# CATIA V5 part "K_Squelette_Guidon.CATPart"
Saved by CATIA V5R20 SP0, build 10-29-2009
Part number: Squelette_Guidon
Bounding box of the stored display mesh (mm): x -220 to 220, y 0 to 0, z 0 to 150
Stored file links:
  G:\Khaled_CFAO_2011\ST2M\ST2M_GR1\bmartinez\Khaled\CAD_ThinkMOTION\K_Squelette_Guidon.CATPart
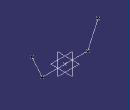
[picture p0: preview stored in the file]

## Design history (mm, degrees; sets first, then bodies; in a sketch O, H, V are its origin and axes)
Set1
  Point1: type OnPlane, Support xy-plane, H 150, V 0, Direction (1, 0, 0)
  Point2: type OnPlane, Support xy-plane, H -150, V 0, Direction (1, 0, 0)
  Line1: type PtPt, FirstPoint Point2, SecondPoint Point1
  Point3: type OnPlane, Support zx-plane, H -220, V 150, Direction (-1, 0, 0)
  Point4: type OnPlane, Support zx-plane, H 220, V 150, Direction (-1, 0, 0)
  Line2: type PtPt, FirstPoint Point4, SecondPoint Point2
  Line3: type PtPt, FirstPoint Point3, SecondPoint Point1
  Point5: (0, 0, 0)
Body1 (main body)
